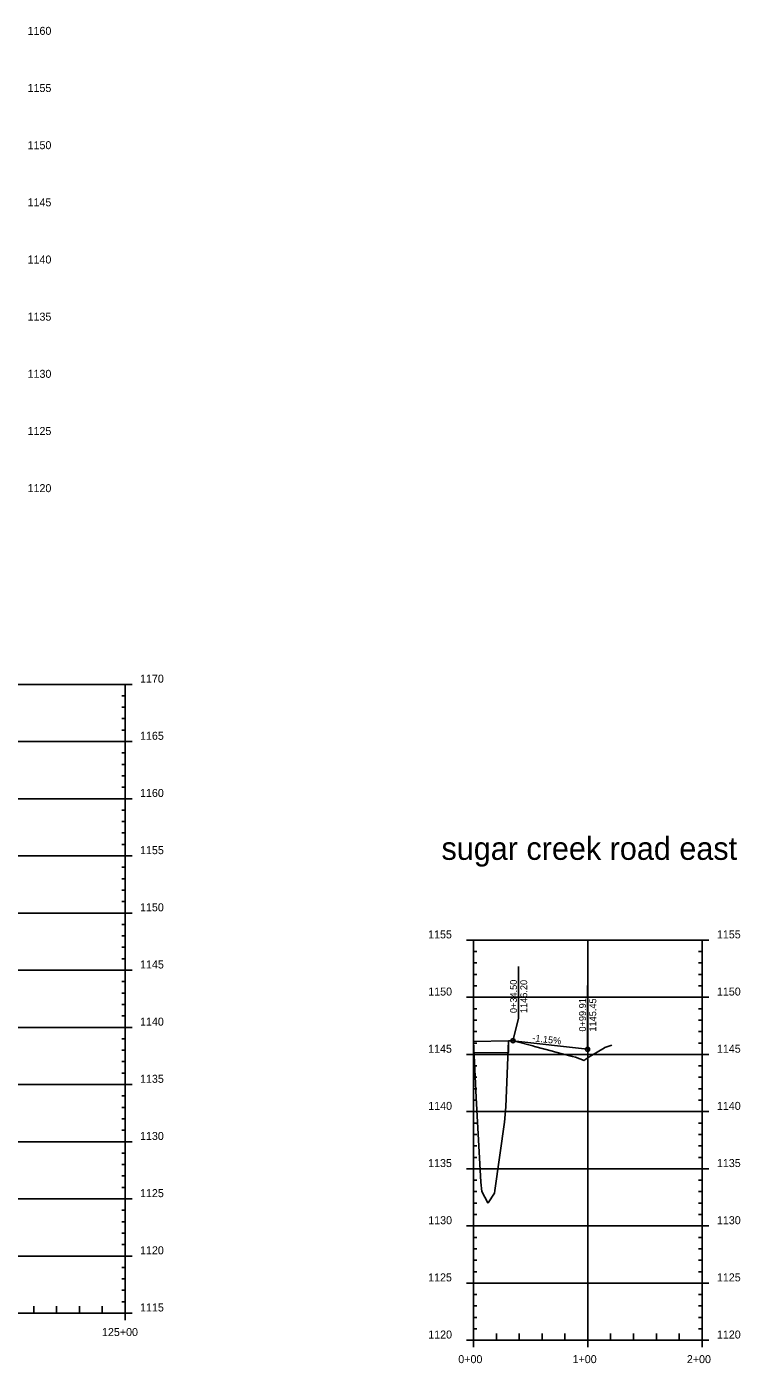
# Model space of a CAD drawing. Extents: x 688474 to 694748, y 765018 to 767373.
# Drawn here: x 693367 to 693992, y 765766 to 766935 of the extents above; entities that cross this region are included whole.
import ezdxf

# ---------------------------------------------------------------- set-up
doc = ezdxf.new("R2010")
doc.units = 0
for name, color, linetype in [('30', 7, 'Continuous'), ('37', 7, 'Continuous'), ('BRIDGE', 7, 'Continuous'), ('R_Exist Surface', 7, 'Continuous'), ('R_Vert Alg', 7, 'Continuous'), ('R_Vert Alg Annot', 7, 'Continuous')]:
    doc.layers.add(name, color=color, linetype=linetype)

msp = doc.modelspace()

# ---------------------------------------------------------------- linework, layer by layer
at = {"layer": '37'}
for p, q in [((690853.6, 766359.9), (693453.6, 766359.9)), ((690853.6, 766359.9), (693453.6, 766359.9)), ((693453.6, 765809.9), (693453.6, 766359.9)), ((693459.6, 766359.9), (693453.6, 766359.9)), ((693459.6, 766359.9), (693453.6, 766359.9)), ((693453.6, 766349.9), (693450.6, 766349.9)), ((693453.6, 766339.9), (693450.6, 766339.9)), ((693453.6, 766329.9), (693450.6, 766329.9)), ((693453.6, 766319.9), (693450.6, 766319.9)), ((690853.6, 766309.9), (693453.6, 766309.9)), ((693459.6, 766309.9), (693453.6, 766309.9)), ((693453.6, 766299.9), (693450.6, 766299.9)), ((693453.6, 766289.9), (693450.6, 766289.9)), ((693453.6, 766279.9), (693450.6, 766279.9)), ((693453.6, 766269.9), (693450.6, 766269.9)), ((690853.6, 766259.9), (693453.6, 766259.9)), ((693459.6, 766259.9), (693453.6, 766259.9)), ((693453.6, 766249.9), (693450.6, 766249.9)), ((693453.6, 766239.9), (693450.6, 766239.9)), ((693453.6, 766229.9), (693450.6, 766229.9)), ((690853.6, 766209.9), (693453.6, 766209.9)), ((693453.6, 766219.9), (693450.6, 766219.9)), ((693459.6, 766209.9), (693453.6, 766209.9)), ((693453.6, 766199.9), (693450.6, 766199.9)), ((693453.6, 766189.9), (693450.6, 766189.9)), ((693453.6, 766179.9), (693450.6, 766179.9)), ((693453.6, 766169.9), (693450.6, 766169.9)), ((690853.6, 766159.9), (693453.6, 766159.9)), ((693459.6, 766159.9), (693453.6, 766159.9)), ((693453.6, 766149.9), (693450.6, 766149.9)), ((693453.6, 766139.9), (693450.6, 766139.9)), ((693453.6, 766129.9), (693450.6, 766129.9)), ((693752.4, 766136.2), (693758.4, 766136.2)), ((693752.4, 766136.2), (693758.4, 766136.2)), ((693758.4, 765786.2), (693758.4, 766136.2)), ((693758.4, 766136.2), (693958.4, 766136.2)), ((693758.4, 766136.2), (693958.4, 766136.2)), ((693858.4, 765786.2), (693858.4, 766136.2)), ((693958.4, 765786.2), (693958.4, 766136.2)), ((693964.4, 766136.2), (693958.4, 766136.2)), ((693964.4, 766136.2), (693958.4, 766136.2)), ((693453.6, 766119.9), (693450.6, 766119.9)), ((693758.4, 766126.2), (693761.4, 766126.2)), ((693958.4, 766126.2), (693955.4, 766126.2)), ((690853.6, 766109.9), (693453.6, 766109.9)), ((693459.6, 766109.9), (693453.6, 766109.9)), ((693758.4, 766116.2), (693761.4, 766116.2)), ((693758.4, 766106.2), (693761.4, 766106.2)), ((693958.4, 766116.2), (693955.4, 766116.2)), ((693958.4, 766106.2), (693955.4, 766106.2)), ((693453.6, 766099.9), (693450.6, 766099.9)), ((693758.4, 766096.2), (693761.4, 766096.2)), ((693958.4, 766096.2), (693955.4, 766096.2)), ((693453.6, 766089.9), (693450.6, 766089.9)), ((693752.4, 766086.2), (693758.4, 766086.2)), ((693758.4, 766086.2), (693958.4, 766086.2)), ((693964.4, 766086.2), (693958.4, 766086.2)), ((693453.6, 766079.9), (693450.6, 766079.9)), ((693453.6, 766069.9), (693450.6, 766069.9)), ((693758.4, 766076.2), (693761.4, 766076.2)), ((693958.4, 766076.2), (693955.4, 766076.2)), ((690853.6, 766059.9), (693453.6, 766059.9)), ((693459.6, 766059.9), (693453.6, 766059.9)), ((693758.4, 766066.2), (693761.4, 766066.2)), ((693958.4, 766066.2), (693955.4, 766066.2)), ((693453.6, 766049.9), (693450.6, 766049.9)), ((693758.4, 766056.2), (693761.4, 766056.2)), ((693958.4, 766056.2), (693955.4, 766056.2)), ((693453.6, 766039.9), (693450.6, 766039.9)), ((693752.4, 766036.2), (693758.4, 766036.2)), ((693758.4, 766046.2), (693761.4, 766046.2)), ((693758.4, 766036.2), (693958.4, 766036.2)), ((693958.4, 766046.2), (693955.4, 766046.2)), ((693964.4, 766036.2), (693958.4, 766036.2)), ((693453.6, 766029.9), (693450.6, 766029.9)), ((693758.4, 766026.2), (693761.4, 766026.2)), ((693958.4, 766026.2), (693955.4, 766026.2)), ((693453.6, 766019.9), (693450.6, 766019.9)), ((693758.4, 766016.2), (693761.4, 766016.2)), ((693958.4, 766016.2), (693955.4, 766016.2)), ((690853.6, 766009.9), (693453.6, 766009.9)), ((693453.6, 765999.9), (693450.6, 765999.9)), ((693459.6, 766009.9), (693453.6, 766009.9)), ((693758.4, 766006.2), (693761.4, 766006.2)), ((693958.4, 766006.2), (693955.4, 766006.2)), ((693453.6, 765989.9), (693450.6, 765989.9)), ((693758.4, 765996.2), (693761.4, 765996.2)), ((693958.4, 765996.2), (693955.4, 765996.2)), ((693453.6, 765979.9), (693450.6, 765979.9)), ((693752.4, 765986.2), (693758.4, 765986.2)), ((693758.4, 765986.2), (693958.4, 765986.2)), ((693758.4, 765976.2), (693761.4, 765976.2)), ((693958.4, 765976.2), (693955.4, 765976.2)), ((693964.4, 765986.2), (693958.4, 765986.2)), ((693453.6, 765969.9), (693450.6, 765969.9)), ((693758.4, 765966.2), (693761.4, 765966.2)), ((693958.4, 765966.2), (693955.4, 765966.2)), ((690853.6, 765959.9), (693453.6, 765959.9)), ((693459.6, 765959.9), (693453.6, 765959.9)), ((693758.4, 765956.2), (693761.4, 765956.2)), ((693958.4, 765956.2), (693955.4, 765956.2)), ((693453.6, 765949.9), (693450.6, 765949.9)), ((693758.4, 765946.2), (693761.4, 765946.2)), ((693958.4, 765946.2), (693955.4, 765946.2)), ((693453.6, 765939.9), (693450.6, 765939.9)), ((693453.6, 765929.9), (693450.6, 765929.9)), ((693752.4, 765936.2), (693758.4, 765936.2)), ((693758.4, 765936.2), (693958.4, 765936.2)), ((693964.4, 765936.2), (693958.4, 765936.2)), ((693453.6, 765919.9), (693450.6, 765919.9)), ((693758.4, 765926.2), (693761.4, 765926.2)), ((693958.4, 765926.2), (693955.4, 765926.2)), ((690853.6, 765909.9), (693453.6, 765909.9)), ((693459.6, 765909.9), (693453.6, 765909.9)), ((693758.4, 765916.2), (693761.4, 765916.2)), ((693758.4, 765906.2), (693761.4, 765906.2)), ((693958.4, 765916.2), (693955.4, 765916.2)), ((693958.4, 765906.2), (693955.4, 765906.2)), ((693453.6, 765899.9), (693450.6, 765899.9)), ((693758.4, 765896.2), (693761.4, 765896.2)), ((693958.4, 765896.2), (693955.4, 765896.2)), ((693453.6, 765889.9), (693450.6, 765889.9)), ((693752.4, 765886.2), (693758.4, 765886.2)), ((693758.4, 765886.2), (693958.4, 765886.2)), ((693964.4, 765886.2), (693958.4, 765886.2)), ((693453.6, 765879.9), (693450.6, 765879.9)), ((693758.4, 765876.2), (693761.4, 765876.2)), ((693958.4, 765876.2), (693955.4, 765876.2)), ((690853.6, 765859.9), (693453.6, 765859.9)), ((693453.6, 765869.9), (693450.6, 765869.9)), ((693459.6, 765859.9), (693453.6, 765859.9)), ((693758.4, 765866.2), (693761.4, 765866.2)), ((693958.4, 765866.2), (693955.4, 765866.2)), ((693453.6, 765849.9), (693450.6, 765849.9)), ((693758.4, 765856.2), (693761.4, 765856.2)), ((693958.4, 765856.2), (693955.4, 765856.2)), ((693453.6, 765839.9), (693450.6, 765839.9)), ((693752.4, 765836.2), (693758.4, 765836.2)), ((693758.4, 765846.2), (693761.4, 765846.2)), ((693758.4, 765836.2), (693958.4, 765836.2)), ((693958.4, 765846.2), (693955.4, 765846.2)), ((693964.4, 765836.2), (693958.4, 765836.2)), ((693453.6, 765829.9), (693450.6, 765829.9)), ((693758.4, 765826.2), (693761.4, 765826.2)), ((693958.4, 765826.2), (693955.4, 765826.2)), ((693373.6, 765809.9), (693373.6, 765815.9)), ((693393.6, 765809.9), (693393.6, 765815.9)), ((693413.6, 765809.9), (693413.6, 765815.9)), ((693433.6, 765809.9), (693433.6, 765815.9)), ((693453.6, 765819.9), (693450.6, 765819.9)), ((693758.4, 765816.2), (693761.4, 765816.2)), ((693958.4, 765816.2), (693955.4, 765816.2)), ((690853.6, 765809.9), (693453.6, 765809.9)), ((693459.6, 765809.9), (693453.6, 765809.9)), ((693453.6, 765803.9), (693453.6, 765809.9)), ((693758.4, 765806.2), (693761.4, 765806.2)), ((693958.4, 765806.2), (693955.4, 765806.2)), ((693758.4, 765796.2), (693761.4, 765796.2)), ((693778.4, 765786.2), (693778.4, 765792.2)), ((693798.4, 765786.2), (693798.4, 765792.2)), ((693818.4, 765786.2), (693818.4, 765792.2)), ((693838.4, 765786.2), (693838.4, 765792.2)), ((693878.4, 765786.2), (693878.4, 765792.2)), ((693898.4, 765786.2), (693898.4, 765792.2)), ((693918.4, 765786.2), (693918.4, 765792.2)), ((693938.4, 765786.2), (693938.4, 765792.2)), ((693958.4, 765796.2), (693955.4, 765796.2)), ((693752.4, 765786.2), (693758.4, 765786.2)), ((693758.4, 765786.2), (693958.4, 765786.2)), ((693758.4, 765780.2), (693758.4, 765786.2)), ((693858.4, 765780.2), (693858.4, 765786.2)), ((693964.4, 765786.2), (693958.4, 765786.2)), ((693958.4, 765780.2), (693958.4, 765786.2))]:
    msp.add_line(p, q, dxfattribs=at)
at = {"layer": 'BRIDGE'}
for p, q in [((693789, 766048), (693758.4, 766047.5)), ((693758.4, 766037.5), (693758.4, 766047.5)), ((693789, 766048), (693789, 766038)), ((693789, 766038), (693758.4, 766037.5))]:
    msp.add_line(p, q, dxfattribs=at)
at = {"layer": 'R_Exist Surface'}
msp.add_lwpolyline([(693758.4, 766047.5), (693758.4, 766047.5), (693760.7, 765998.5), (693761.2, 765987.7), (693764.9, 765924.6), (693765.8, 765916.3), (693771, 765906.5), (693771.1, 765906.3), (693771.2, 765906.4), (693776.7, 765915), (693777, 765917.3), (693785.6, 765977), (693786.7, 765990.4), (693789, 766048), (693789, 766048), (693792.9, 766048.2), (693794.4, 766047.8), (693810.3, 766043.6), (693811.8, 766043.2), (693827.6, 766039), (693829.2, 766038.6), (693845.1, 766034.3), (693847.7, 766033.7), (693855.2, 766030.9), (693855.8, 766031.4), (693861.2, 766035), (693861.8, 766035.4), (693873, 766042.1), (693873.4, 766042.2), (693876.9, 766043.5), (693879.4, 766044.4)], dxfattribs=at)
msp.add_lwpolyline([(693758.4, 766047.5), (693758.4, 766047.5), (693760.7, 765998.5), (693761.2, 765987.7), (693764.9, 765924.6), (693765.8, 765916.3), (693771, 765906.5), (693771.1, 765906.3), (693771.2, 765906.4), (693776.7, 765915), (693777, 765917.3), (693785.6, 765977), (693786.7, 765990.4), (693789, 766048), (693789, 766048), (693792.9, 766048.2), (693794.4, 766047.8), (693810.3, 766043.6), (693811.8, 766043.2), (693827.6, 766039), (693829.2, 766038.6), (693845.1, 766034.3), (693847.7, 766033.7), (693855.2, 766030.9), (693855.8, 766031.4), (693861.2, 766035), (693861.8, 766035.4), (693873, 766042.1), (693873.4, 766042.2), (693876.9, 766043.5), (693879.4, 766044.4)], dxfattribs=at)
at = {"layer": 'R_Vert Alg'}
msp.add_line((693792.9, 766048.2), (693858.3, 766040.7), dxfattribs=at)
for centre in [(693792.9, 766048.2), (693858.3, 766040.7)]:
    msp.add_circle(centre, 1.75, dxfattribs=at)
at = {"layer": 'R_Vert Alg Annot'}
msp.add_line((693858.3, 766040.7), (693858.3, 766096.6), dxfattribs=at)
msp.add_lwpolyline([(693792.9, 766048.2), (693797.9, 766067.5), (693797.9, 766113.2)], dxfattribs=at)

# ---------------------------------------------------------------- texts
at = {"layer": '30'}
for s, p in [('1160', (693368.2, 766928)), ('1160', (693368.2, 766928)), ('1155', (693368.2, 766878)), ('1150', (693368.2, 766828)), ('1145', (693368.2, 766778)), ('1140', (693368.2, 766728)), ('1135', (693368.2, 766678)), ('1130', (693368.2, 766628)), ('1125', (693368.2, 766578)), ('1120', (693368.2, 766528)), ('1170', (693466.6, 766361.4)), ('1170', (693466.6, 766361.4)), ('1165', (693466.6, 766311.4)), ('1160', (693466.6, 766261.4)), ('1155', (693466.6, 766211.4)), ('1150', (693466.6, 766161.4)), ('1155', (693718.7, 766137.7)), ('1155', (693718.7, 766137.7)), ('1155', (693971.4, 766137.7)), ('1155', (693971.4, 766137.7)), ('1145', (693466.6, 766111.4)), ('1150', (693718.8, 766087.7)), ('1150', (693971.4, 766087.7)), ('1140', (693466.6, 766061.4)), ('1145', (693718.7, 766037.7)), ('1145', (693971.4, 766037.7)), ('1135', (693466.6, 766011.4)), ('1140', (693718.8, 765987.7)), ('1140', (693971.4, 765987.7)), ('1130', (693466.6, 765961.4)), ('1135', (693718.7, 765937.7)), ('1135', (693971.4, 765937.7)), ('1125', (693466.6, 765911.4)), ('1130', (693718.8, 765887.7)), ('1130', (693971.4, 765887.7)), ('1120', (693466.6, 765861.4)), ('1125', (693718.7, 765837.7)), ('1125', (693971.4, 765837.7)), ('1115', (693466.6, 765811.4)), ('125+00', (693433.3, 765789.9)), ('1120', (693718.8, 765787.7)), ('1120', (693971.4, 765787.7)), ('0+00', (693745.1, 765766.2)), ('1+00', (693845.1, 765766.2)), ('2+00', (693945.1, 765766.2))]:
    msp.add_text(s, height=7, dxfattribs=at).set_placement(p)
at = {"layer": 'R_Vert Alg Annot'}
msp.add_text('sugar creek road east', height=20, dxfattribs=at).set_placement((693730.4, 766206.4))
for s, rotation, p in [('0+34.50', 90, (693796.4, 766072.4)), ('1146.20', 90, (693805.4, 766072.4)), ('0+99.91', 90, (693856.8, 766056.2)), ('1145.45', 90, (693865.8, 766056.2)), ('-1.15%', 353.459, (693809.6, 766047.8))]:
    msp.add_text(s, height=6, rotation=rotation, dxfattribs=at).set_placement(p)

doc.saveas('drawing.dxf')
